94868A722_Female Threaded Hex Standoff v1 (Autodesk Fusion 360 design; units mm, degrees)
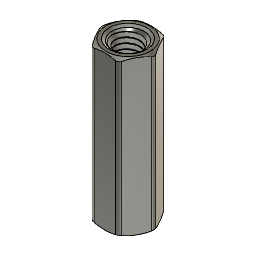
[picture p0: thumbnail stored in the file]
description: STEP AP203
part number: 94868A722_Female Threaded Hex Standoff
